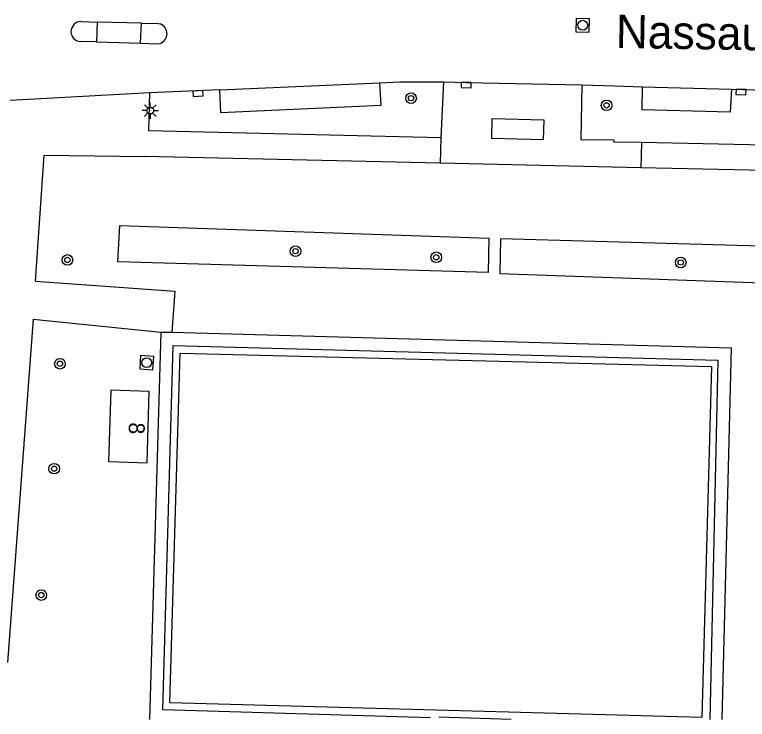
# Model space of a CAD drawing. Extents: x 132573 to 132944, y 398226 to 398676.
# Drawn here: x 132817.6 to 132872.8, y 398226.3 to 398279.4 of the extents above; entities that cross this region are included whole.
import ezdxf

# ---------------------------------------------------------------- set-up
doc = ezdxf.new("R2010")
doc.units = 0
for name, color, linetype in [('gg-afsc-hekwerk', 7, 'Continuous'), ('gg-anno-openbare ruimte label', 7, 'Continuous'), ('gg-bbg-abri', 7, 'Continuous'), ('gg-knt-verharding', 7, 'Continuous'), ('gg-knt-verharding nz', 7, 'Continuous'), ('gt-anno-plantopografie huisnummer', 7, 'Continuous'), ('gt-bbg-plantopografie pand', 7, 'Continuous'), ('gt-grn-groengrens', 7, 'Continuous'), ('gt-symb-boom', 7, 'Continuous'), ('gt-symb-kolk', 7, 'Continuous'), ('gt-symb-lichtmast', 7, 'Continuous'), ('gt-symb-rioolschacht', 7, 'Continuous')]:
    doc.layers.add(name, color=color, linetype=linetype)

msp = doc.modelspace()

# ---------------------------------------------------------------- linework, layer by layer
at = {"layer": 'gg-afsc-hekwerk'}
msp.add_line((132855.011, 398226.299), (132849.56, 398226.465), dxfattribs=at)
msp.add_lwpolyline([(132848.91, 398226.417), (132828.744, 398227.018), (132829.507, 398254.484), (132870.588, 398253.38), (132869.995, 398226.299)], dxfattribs=at)
at = {"layer": 'gg-bbg-abri'}
msp.add_line((132857.428, 398269.988), (132853.546, 398270.073), dxfattribs=at)
msp.add_lwpolyline([(132853.546, 398270.073), (132853.578, 398271.572), (132857.466, 398271.48), (132857.428, 398269.988)], dxfattribs=at)
at = {"layer": 'gg-knt-verharding'}
for p, q in [((132822.582, 398278.889), (132823.785, 398278.834)), ((132823.785, 398278.834), (132823.723, 398277.352)), ((132827.134, 398278.758), (132823.785, 398278.834)), ((132827.055, 398277.251), (132827.134, 398278.758)), ((132823.723, 398277.352), (132822.491, 398277.378)), ((132823.723, 398277.352), (132827.055, 398277.251)), ((132833.031, 398273.745), (132845.079, 398274.279)), ((132849.906, 398274.353), (132849.7, 398270.12)), ((132860.332, 398274.127), (132860.251, 398270.005)), ((132827.748, 398273.511), (132817.229, 398272.946)), ((132833.031, 398273.745), (132827.748, 398273.511)), ((132864.92, 398273.976), (132871.622, 398273.797)), ((132871.622, 398273.797), (132896.134, 398273.123)), ((132864.837, 398269.763), (132862.745, 398269.806)), ((132896.036, 398269.121), (132864.837, 398269.763)), ((132819.143, 398259.319), (132819.796, 398268.823)), ((132819.796, 398268.823), (132827.354, 398268.722)), ((132849.656, 398268.212), (132827.354, 398268.722)), ((132864.794, 398267.865), (132849.656, 398268.212)), ((132899.13, 398267.08), (132864.794, 398267.865)), ((132818.966, 398256.451), (132817.017, 398230.579)), ((132818.966, 398256.451), (132828.574, 398255.492)), ((132828.574, 398255.492), (132827.719, 398226.299)), ((132828.574, 398255.492), (132829.409, 398255.469))]:
    msp.add_line(p, q, dxfattribs=at)
for points in [[(132827.134, 398278.758), (132828.386, 398278.742), (132828.53, 398278.708)], [(132827.055, 398277.251), (132828.283, 398277.208), (132828.527, 398277.247)], [(132845.079, 398274.279), (132845.182, 398272.564), (132833.107, 398272.006), (132833.031, 398273.745)], [(132845.079, 398274.279), (132846.598, 398274.346), (132849.906, 398274.353)], [(132849.906, 398274.353), (132851.614, 398274.3), (132860.332, 398274.127)], [(132860.332, 398274.127), (132862.78, 398274.033), (132864.92, 398273.976)], [(132849.7, 398270.12), (132827.67, 398270.66), (132827.748, 398273.511)], [(132871.622, 398273.797), (132871.525, 398272.062), (132864.888, 398272.247), (132864.92, 398273.976)], [(132860.251, 398270.005), (132862.747, 398269.968), (132862.745, 398269.806)], [(132819.143, 398259.319), (132829.629, 398258.575), (132829.409, 398255.469)], [(132829.409, 398255.469), (132871.599, 398254.289), (132870.89, 398226.299)], [(132829.267, 398227.539), (132830.034, 398253.893), (132870.106, 398252.894), (132869.371, 398226.434), (132829.267, 398227.539)]]:
    msp.add_lwpolyline(points, dxfattribs=at)
for centre, radius, start, end in [((132822.565, 398278.133), 0.757, 88.6825, 180.4974), ((132828.284, 398277.978), 0.77, 288.4223, 71.3424), ((132822.565, 398278.131), 0.757, 180.3943, 264.4042)]:
    msp.add_arc(centre, radius, start, end, dxfattribs=at)
at = {"layer": 'gg-knt-verharding nz'}
for p, q in [((132849.7, 398270.12), (132849.656, 398268.212)), ((132864.837, 398269.763), (132864.794, 398267.865))]:
    msp.add_line(p, q, dxfattribs=at)
at = {"layer": 'gt-bbg-plantopografie pand'}
msp.add_lwpolyline([(132827.543, 398245.639), (132827.701, 398251.016), (132824.802, 398251.101), (132824.645, 398245.723), (132827.543, 398245.639)], dxfattribs=at)
at = {"layer": 'gt-grn-groengrens'}
for points in [[(132825.344, 398260.791), (132825.498, 398263.526), (132853.321, 398262.575), (132853.275, 398259.968), (132825.344, 398260.791)], [(132854.2, 398262.504), (132854.161, 398259.901), (132891.539, 398258.578), (132891.698, 398261.456), (132854.2, 398262.504)]]:
    msp.add_lwpolyline(points, dxfattribs=at)
at = {"layer": 'gt-symb-boom'}
for centre, radius in [((132847.457, 398273.113), 0.4), ((132847.457, 398273.113), 0.2), ((132862.203, 398272.574), 0.4), ((132862.203, 398272.574), 0.2), ((132838.739, 398261.582), 0.4), ((132821.541, 398260.921), 0.4), ((132838.739, 398261.582), 0.2), ((132849.358, 398261.122), 0.4), ((132849.358, 398261.122), 0.2), ((132821.541, 398260.921), 0.2), ((132867.791, 398260.732), 0.4), ((132867.791, 398260.732), 0.2), ((132820.978, 398253.1), 0.4), ((132820.978, 398253.1), 0.2), ((132820.545, 398245.192), 0.4), ((132820.545, 398245.192), 0.2), ((132819.57, 398235.665), 0.4), ((132819.57, 398235.665), 0.2)]:
    msp.add_circle(centre, radius, dxfattribs=at)
at = {"layer": 'gt-symb-kolk'}
for points in [[(132851.614, 398274.3), (132851.239, 398274.307), (132851.231, 398273.908), (132851.981, 398273.893), (132851.989, 398274.293), (132851.614, 398274.3)], [(132831.372, 398273.665), (132830.997, 398273.647), (132831.017, 398273.247), (132831.766, 398273.283), (132831.747, 398273.683), (132831.372, 398273.665)], [(132872.345, 398273.775), (132871.97, 398273.785), (132871.959, 398273.385), (132872.709, 398273.365), (132872.72, 398273.765), (132872.345, 398273.775)]]:
    msp.add_lwpolyline(points, dxfattribs=at)
at = {"layer": 'gt-symb-lichtmast'}
for p, q in [((132827.613, 398272.352), (132827.348, 398272.617)), ((132827.79, 398272.425), (132827.79, 398272.8)), ((132827.967, 398272.352), (132828.232, 398272.617)), ((132827.54, 398272.175), (132827.165, 398272.175)), ((132827.613, 398271.998), (132827.348, 398271.733)), ((132827.79, 398271.925), (132827.79, 398271.55)), ((132828.232, 398271.733), (132827.967, 398271.998)), ((132828.04, 398272.175), (132828.415, 398272.175))]:
    msp.add_line(p, q, dxfattribs=at)
msp.add_circle((132827.79, 398272.175), 0.25, dxfattribs=at)
at = {"layer": 'gt-symb-rioolschacht'}
for points in [[(132859.884, 398278.126), (132860.884, 398278.094), (132860.916, 398279.094), (132859.916, 398279.126)], [(132827.992, 398252.65), (132828.053, 398253.649), (132827.054, 398253.71), (132826.993, 398252.711)]]:
    msp.add_lwpolyline(points, close=True, dxfattribs=at)
for centre in [(132860.4, 398278.61), (132827.523, 398253.18)]:
    msp.add_circle(centre, 0.375, dxfattribs=at)

# ---------------------------------------------------------------- texts
at = {"layer": 'gg-anno-openbare ruimte label'}
msp.add_text('Nassauplein', height=2.5, rotation=359, dxfattribs=at).set_placement((132862.882, 398276.915))
at = {"layer": 'gt-anno-plantopografie huisnummer'}
msp.add_text('8', height=1.2, rotation=268.3212, dxfattribs=at).set_placement((132826.182, 398248.692))

doc.saveas('drawing.dxf')
